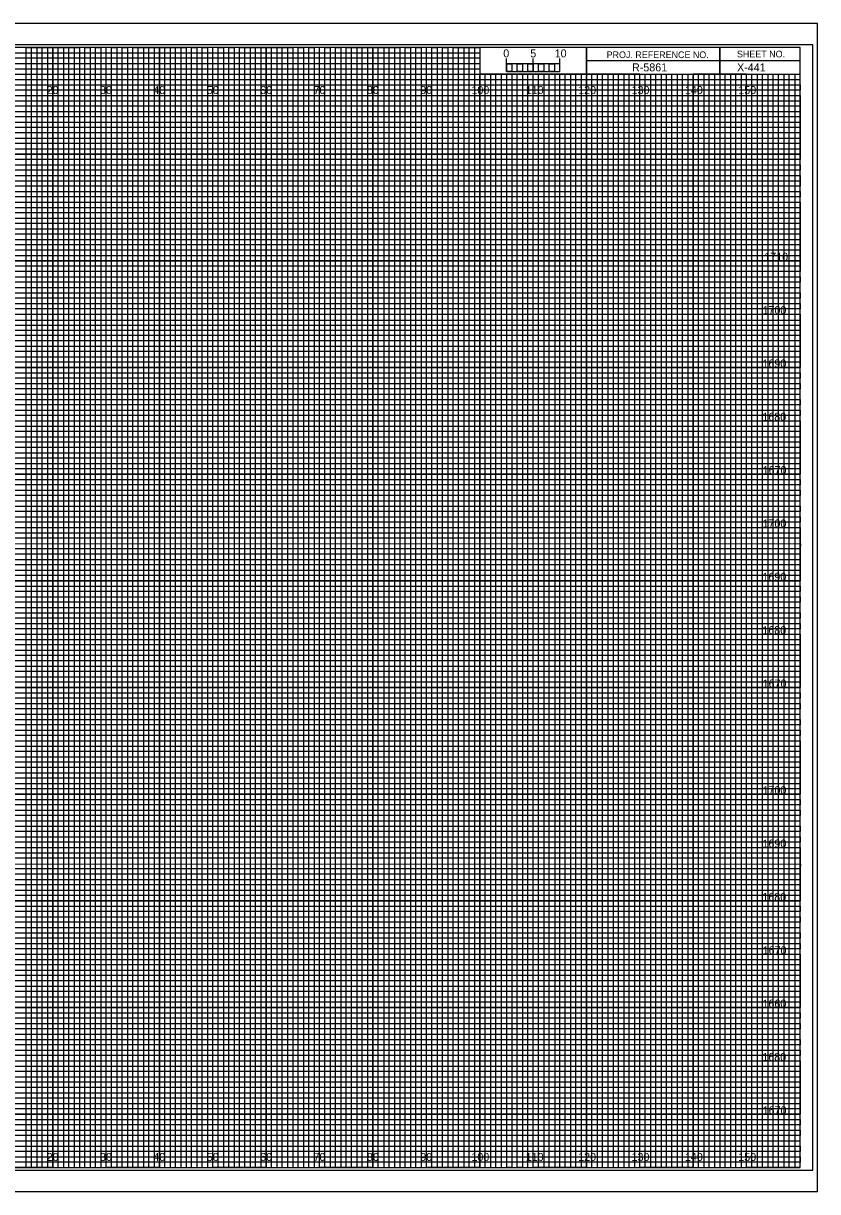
# Model space of a CAD drawing. Extents: x -13 to 323, y -5 to 1314.
# Drawn here: x 174.5 to 323.3, y -4.5 to 214.5 of the extents above; entities that cross this region are included whole.
import ezdxf

# ---------------------------------------------------------------- set-up
doc = ezdxf.new("R2010")
doc.units = 0
for name, color, linetype in [('Prop XS Bar Scale Labels', 7, 'Continuous'), ('Prop XS Project Number', 7, 'Continuous'), ('Prop XS Sheet Number', 7, 'Continuous'), ('Raster_Level_0', 7, 'Continuous'), ('Scratch_Level_3', 7, 'Continuous'), ('Sheet Cross Section CELL', 7, 'Continuous'), ('Sheet Cross Section Grid Major CELL', 7, 'Continuous'), ('Sheet Cross Section Grid Middle CELL', 7, 'Continuous'), ('Sheet Cross Section Grid Minor 1 CELL', 7, 'Continuous'), ('Sheet Cross Section Grid Minor 2 CELL', 7, 'Continuous'), ('Sheet Cross Section Scale CELL', 7, 'Continuous'), ('Sheet Cutting Line CELL', 7, 'Continuous'), ('Sheet DOT Grid CELL', 7, 'Continuous'), ('Sheet Plot Border Inside CELL', 7, 'Continuous'), ('Sheet Plot Border Outside CELL', 7, 'Continuous')]:
    doc.layers.add(name, color=color, linetype=linetype)

msp = doc.modelspace()

# ---------------------------------------------------------------- linework, layer by layer
at = {"layer": 'Sheet Cross Section CELL'}
for p, q in [((305, 210), (305, 205)), ((305, 205), (305, 210)), ((280, 207.5), (280, 205)), ((320, 207.49), (280, 207.49)), ((280, 205), (320, 205))]:
    msp.add_line(p, q, dxfattribs=at)
for points in [[(320, 210), (0, 210), (0, 0), (320, 0)], [(280, 210), (260, 210), (260, 205.03), (280, 205.03)], [(320, 210), (280, 210), (280, 205), (320, 205)]]:
    msp.add_lwpolyline(points, close=True, dxfattribs=at)
at = {"layer": 'Sheet Cross Section Grid Major CELL'}
for p, q in [((190, 210), (180, 210)), ((180, 210), (180, 0)), ((190, 0), (190, 210)), ((210, 210), (200, 210)), ((200, 210), (200, 0)), ((210, 0), (210, 210)), ((230, 210), (220, 210)), ((220, 210), (220, 0)), ((230, 0), (230, 210)), ((250, 210), (240, 210)), ((240, 210), (240, 0)), ((250, 0), (250, 210)), ((260, 210), (260, 0)), ((270, 0), (270, 205)), ((290, 205), (280, 205)), ((280, 205), (280, 0)), ((290, 0), (290, 205)), ((310, 205), (300, 205)), ((300, 205), (300, 0)), ((310, 0), (310, 205)), ((180, 0), (170, 0)), ((200, 0), (190, 0)), ((220, 0), (210, 0)), ((240, 0), (230, 0)), ((260, 0), (250, 0)), ((280, 0), (270, 0)), ((300, 0), (290, 0)), ((320, 0), (310, 0)), ((320, 0), (320, 0))]:
    msp.add_line(p, q, dxfattribs=at)
for points in [[(0, 200), (320, 200), (320, 190), (0, 190)], [(0, 180), (320, 180), (320, 170), (0, 170)], [(0, 160), (320, 160), (320, 150), (0, 150)], [(0, 140), (320, 140), (320, 130), (0, 130)], [(0, 120), (320, 120), (320, 110), (0, 110)], [(0, 100), (320, 100), (320, 90), (0, 90)], [(0, 80), (320, 80), (320, 70), (0, 70)], [(0, 60), (320, 60), (320, 50), (0, 50)], [(0, 40), (320, 40), (320, 30), (0, 30)], [(0, 20), (320, 20), (320, 10), (0, 10)]]:
    msp.add_lwpolyline(points, dxfattribs=at)
at = {"layer": 'Sheet Cross Section Grid Middle CELL'}
for points in [[(165, 0), (175, 0), (175, 210), (185, 210), (185, 0), (195, 0), (195, 210), (205, 210), (205, 0), (215, 0), (215, 210), (225, 210), (225, 0), (235, 0), (235, 210), (245, 210), (245, 0), (255, 0), (255, 210), (259.93, 210), (260, 210), (260, 205), (264.99, 205), (264.99, 0), (275, 0), (275, 205), (285, 205), (285, 0), (295, 0), (295, 205), (305, 205), (305, 0), (315, 0), (315, 205)], [(0, 205), (275, 205)], [(0, 185), (320, 185), (320, 195), (0, 195)], [(0, 165), (320, 165), (320, 175), (0, 175)], [(0, 145), (320, 145), (320, 155), (0, 155)], [(0, 125), (320, 125), (320, 135), (0, 135)], [(0, 105), (320, 105), (320, 115), (0, 115)], [(0, 85), (320, 85), (320, 95), (0, 95)], [(0, 65), (320, 65), (320, 75), (0, 75)], [(0, 45), (320, 45), (320, 55), (0, 55)], [(0, 25), (320, 25), (320, 35), (0, 35)], [(0, 5), (320, 5), (320, 15), (0, 15)]]:
    msp.add_lwpolyline(points, dxfattribs=at)
at = {"layer": 'Sheet Cross Section Grid Minor 1 CELL'}
for p, q in [((0, 209), (260, 209)), ((260, 209), (260, 207.98)), ((260, 207.98), (0, 207.98)), ((0, 207), (260, 207)), ((260, 205.89), (0, 205.89)), ((260, 207), (260, 205.89)), ((0, 204), (320, 204))]:
    msp.add_line(p, q, dxfattribs=at)
for points in [[(0, 203), (270, 203), (320, 203), (320, 202), (0, 202)], [(0, 201), (320, 201), (320, 199), (0, 199)], [(0, 198), (320, 198), (320, 197), (0, 196.98)], [(0, 196), (320, 196), (320, 194), (0, 194)], [(0, 193), (320, 193), (320, 192), (0, 192)], [(0, 191), (320, 191), (320, 189), (0, 189)], [(0, 188), (320, 188), (320, 187), (0, 187)], [(0, 186), (320, 186), (320, 184), (0, 184)], [(0, 183), (320, 183), (320, 182), (0, 182)], [(0, 181), (320, 181), (320, 179), (0, 179)], [(0, 178), (320, 178), (320, 177), (0, 177)], [(0, 176), (320, 176), (320, 173.95), (320, 173), (320, 172), (0, 172)], [(0, 174), (320, 174), (320, 173), (0, 173)], [(0, 171), (320, 171), (320, 169), (0, 169.03)], [(0, 169.03), (320, 169), (320, 168), (0, 168)], [(0, 167), (320, 167), (320, 166), (0, 166)], [(0, 164), (320, 164), (320, 163), (0, 163)], [(0, 162), (320, 162), (320, 161), (0, 161)], [(-0.07, 158.89), (320, 158.89), (320, 157.88), (-0.07, 157.88)], [(0, 157), (320, 157), (320, 156), (0, 156)], [(0, 154), (320, 154), (320, 153), (0, 153)], [(0, 152), (320, 152), (320, 151), (0, 151)], [(0, 149), (320, 149), (320, 148), (0, 148)], [(0, 147), (320, 147), (320, 146), (0, 146)], [(0, 144), (320, 144), (320, 143), (0, 143)], [(0, 142), (320, 142), (320, 141), (0, 141)], [(0, 139), (320, 139), (319.99, 137.98), (0, 138)], [(0, 137), (320, 137), (320, 136), (0, 136)], [(0, 134), (320, 134), (320, 133), (0, 133)], [(0, 132), (320, 132), (320, 131), (0, 131)], [(0, 129), (320, 129), (320, 128), (0, 128)], [(0, 127), (320, 127), (320, 126), (0, 126)], [(0, 124), (320, 124), (320, 123), (0, 123)], [(0, 122), (320, 122), (320, 121), (0, 121)], [(0, 119), (320, 119), (320, 118), (0, 118)], [(0, 116.99), (320.07, 116.91), (320, 116), (0, 116)], [(0, 114), (320, 114), (320, 113), (0, 113)], [(0, 112), (320, 112), (320, 111), (0, 111)], [(0, 109), (320, 109), (320, 108), (0, 108)], [(0, 107), (320, 107), (320, 106), (0, 106)], [(0, 104), (320, 104), (320, 103), (0, 103)], [(0, 102), (320, 102), (320, 101), (0, 101)], [(0, 99), (320, 99), (320, 98), (0, 98)], [(0, 97), (320, 97), (320, 96), (0, 96)], [(0, 94), (320, 94), (320, 93), (0, 93)], [(0, 92), (320, 92), (320, 91), (0, 91)], [(0, 89), (320, 89), (320, 88), (0, 88)], [(0, 87), (320, 87), (320, 86), (0, 86)], [(0, 84), (320, 84), (320, 83), (0, 83)], [(0, 82), (320, 82), (320, 81), (0, 81)], [(0, 79), (320, 79), (319.99, 77.98), (0, 78)], [(0, 77), (320, 77), (320, 76), (0, 76)], [(0, 74), (320, 74), (320, 73), (0, 73)], [(0, 72), (320, 72), (320, 71), (0, 71)], [(0, 69), (320, 69), (320, 68), (0, 68)], [(0, 67), (320, 67), (320, 66), (0, 66)], [(0, 64), (320, 64), (320, 63), (0, 63)], [(0, 62), (320, 62), (320, 61), (0, 61)], [(0, 59), (320, 59), (320, 58), (0, 58)], [(0, 56.99), (320.07, 56.91), (320, 56), (0, 56)], [(0, 54), (320, 54), (320, 53), (0, 53)], [(0, 52), (320, 52), (320, 51), (0, 51)], [(0, 49), (320, 49), (320, 48), (0, 48)], [(0, 47), (320, 47), (320, 46), (0, 46)], [(0, 44), (320, 44), (320, 43), (0, 43)], [(0, 42), (320, 42), (320, 41), (0, 41)], [(0, 39), (320, 39), (320, 38), (0, 38)], [(0, 37), (320, 37), (320, 36), (0, 36)], [(0, 34), (320, 34), (320, 33), (0, 33)], [(0, 32), (320, 32), (320, 31), (0, 31)], [(0, 29), (320, 29), (320, 28), (0, 28)], [(0, 27), (320, 27), (320, 26), (0, 26)], [(0, 24), (320, 24), (320, 23), (0, 23)], [(0, 22), (320, 22), (320, 21), (0, 21)], [(0, 19), (320, 19), (320, 18), (0, 18)], [(0, 17), (320, 17), (320, 16), (0, 16)], [(0, 14), (320, 14), (320, 13), (0, 13)], [(0, 12), (320, 12), (320, 11), (0, 11)], [(0, 9), (320, 9), (320, 8), (0, 8)], [(0, 7), (320, 7), (320, 6), (0, 6)], [(0, 4), (320, 4), (320, 3), (0, 3)], [(0, 2), (320, 2), (320, 1), (0, 1)]]:
    msp.add_lwpolyline(points, dxfattribs=at)
at = {"layer": 'Sheet Cross Section Grid Minor 2 CELL'}
for p, q in [((267, 205), (266.01, 205)), ((266.01, 205), (266.01, 0)), ((267, 0), (267, 205)), ((269, 205), (268, 205)), ((268, 205), (268, 0)), ((269, 0), (269, 205)), ((266.01, 0), (265, 0)), ((268, 0), (267, 0))]:
    msp.add_line(p, q, dxfattribs=at)
for points in [[(175, 0), (176, 0), (176, 210), (177, 210), (177, 0)], [(177, 0), (178, 0), (178, 210), (179, 210), (179, 0)], [(180, 0), (181, 0), (181, 210), (182, 210), (182, 0)], [(182, 0), (183, 0), (183, 210), (184, 210), (184, 0)], [(185, 0), (186, 0), (186, 210), (187, 210), (187, 0)], [(187, 0), (188, 0), (188, 210), (189, 210), (189, 0)], [(190, 0), (191, 0), (191, 210), (192, 210), (192, 0)], [(192, 0), (193, 0), (193, 210), (194, 210), (194, 0)], [(195, 0), (196, 0), (196, 210), (197, 210), (197, 0)], [(197, 0), (198, 0), (198, 210), (199, 210), (199, 0)], [(200, 0), (201, 0), (201, 210), (202, 210), (202, 0)], [(202, 0), (203, 0), (203, 210), (204, 210), (204, 0)], [(205, 0), (206, 0), (206, 210), (207, 210), (207, 0)], [(207, 0), (208, 0), (208, 210), (209, 210), (209, 0)], [(210, 0), (211, 0), (211, 210), (212, 210), (212, 0)], [(212, 0), (213, 0), (213, 210), (214, 210), (214, 0)], [(215, 0), (216, 0), (216, 210), (217, 210), (217, 0)], [(217, 0), (218, 0), (218, 210), (219, 210), (219, 0)], [(220, 0), (221, 0), (221, 210), (222, 210), (222, 0)], [(222, 0), (223, 0), (223, 210), (224, 210), (224, 0)], [(225, 0), (226, 0), (226, 210), (227, 210), (227, 0)], [(227, 0), (228, 0), (228, 210), (229, 210), (229, 0)], [(230, 0), (231, 0), (231, 210), (232, 210), (232, 0)], [(232, 0), (233, 0), (233, 210), (234, 210), (234, 0)], [(235, 0), (236, 0), (236, 210), (237, 210), (237, 0)], [(237, 0), (238, 0), (238, 210), (239, 210), (239, 0)], [(240, 0), (241, 0), (241, 210), (242, 210), (242, 0)], [(242, 0), (243, 0), (243, 210), (244, 210), (244, 0)], [(245, 0), (246, 0), (246, 210), (247, 210), (247, 0)], [(247, 0), (248, 0), (248, 210), (249, 210), (249, 0)], [(250, 0), (251, 0), (251, 210), (252, 210), (252, 0)], [(252, 0), (253, 0), (253, 210), (254, 210), (254, 0)], [(255, 0), (256, 0), (256, 210), (257, 210), (257, 0)], [(257, 0), (258, 0), (258, 210), (259, 210), (259, 0)], [(260, 0), (261, 0), (261, 205), (262.02, 205), (262.02, 0)], [(262, 0), (263, 0), (263, 205), (263.99, 205), (263.99, 0)], [(270, 0), (270.98, 0), (270.98, 205), (272, 205), (272, 0)], [(272, 0), (273, 0), (273, 205), (274.05, 205), (274.05, 0)], [(275, 0), (276, 0), (276, 205), (277, 205), (277, 0)], [(277, 0), (278, 0), (278, 205), (279, 205), (279, 0)], [(280, 0), (281, 0), (281, 205), (282, 205), (282, 0)], [(282, 0), (283, 0), (283, 205), (284, 205), (284, 0)], [(285, 0), (286, 0), (286, 205), (287, 205), (287, 0)], [(287, 0), (288, 0), (288, 205), (289, 205), (289, 0)], [(290, 0), (291, 0), (291, 205), (292, 205), (292, 0)], [(292, 0), (293, 0), (293, 205), (294, 205), (294, 0)], [(295, 0), (296, 0), (296, 205), (297, 205), (297, 0)], [(297, 0), (298, 0), (298, 205), (299, 205), (299, 0)], [(300, 0), (301, 0), (301, 205), (302, 205), (302, 0)], [(302, 0), (303, 0), (303, 205), (304, 205), (304, 0)], [(305, 0), (306, 0), (306, 205), (307, 205), (307, 0)], [(307, 0), (308, 0), (308, 205), (309, 205), (309, 0)], [(310, 0), (311, 0), (311, 205), (312, 205), (312, 0)], [(312, 0), (313, 0), (313, 205), (314, 205), (314, 0)], [(315, 0), (316, 0), (316, 205), (317, 205), (317, 0)], [(317, 0), (318, 0), (318, 205), (319, 205), (319, 0)]]:
    msp.add_lwpolyline(points, dxfattribs=at)
at = {"layer": 'Sheet Cross Section Scale CELL'}
for p, q in [((265, 205.49), (265, 207.9)), ((265, 206.9), (265, 207.9)), ((270, 205.49), (270, 207.9)), ((275, 205.49), (275, 207.9)), ((275, 206.9), (275, 207.9))]:
    msp.add_line(p, q, dxfattribs=at)
for points in [[(275, 206.9), (265, 206.9), (265, 205.49), (275, 205.49)], [(265, 206.9), (266, 206.9), (266, 205.49), (265, 205.49)], [(267, 206.9), (268, 206.9), (268, 205.49), (267, 205.49)], [(269, 206.9), (270, 206.9), (270, 205.49), (269, 205.49)], [(271, 206.9), (272, 206.9), (272, 205.49), (271, 205.49)], [(273, 206.9), (274, 206.9), (274, 205.49), (273, 205.49)]]:
    msp.add_lwpolyline(points, close=True, dxfattribs=at)
at = {"layer": 'Sheet Cutting Line CELL'}
for p, q in [((323.3, 214.5), (-13.4, 214.5)), ((-13.4, -4.5), (323.3, -4.5))]:
    msp.add_line(p, q, dxfattribs=at)
at = {"layer": 'Sheet DOT Grid CELL'}
for p, q in [((180, 0), (180, 210)), ((190, 0), (190, 210)), ((200, 0), (200, 210)), ((210, 0), (210, 210)), ((220, 0), (220, 210)), ((230, 0), (230, 210)), ((240, 0), (240, 210)), ((250, 0), (250, 210)), ((260, 0), (260, 204.69)), ((270, 0), (270, 204.69)), ((280, 0), (280, 204.69)), ((290, 0), (290, 204.69)), ((300, 0), (300, 204.69)), ((310, 0), (310, 204.69)), ((0, 200), (320, 200)), ((0, 190), (320, 190)), ((0, 180), (320, 180)), ((0, 170), (320, 170)), ((0, 160), (320, 160)), ((0, 150), (320, 150)), ((0, 140), (320, 140)), ((0, 130), (320, 130)), ((0, 120), (320, 120)), ((0, 110), (320, 110)), ((0, 100), (320, 100)), ((0, 90), (320, 90)), ((0, 80), (320, 80)), ((0, 70), (320, 70)), ((0, 60), (320, 60)), ((0, 50), (320, 50)), ((0, 40), (320, 40)), ((0, 30), (320, 30)), ((0, 20), (320, 20)), ((0, 10), (320, 10))]:
    msp.add_line(p, q, dxfattribs=at)
at = {"layer": 'Sheet Plot Border Inside CELL'}
msp.add_lwpolyline([(-10.8, -0.5), (322.4, -0.5), (322.4, 210.5), (-10.8, 210.5)], close=True, dxfattribs=at)
at = {"layer": 'Sheet Plot Border Outside CELL'}
msp.add_lwpolyline([(-13.4, -4.5), (323.3, -4.5), (323.3, 214.5), (-13.4, 214.5)], close=True, dxfattribs=at)

# ---------------------------------------------------------------- texts
at = {"layer": 'Prop XS Bar Scale Labels'}
for s, p in [('5', (269.47, 208.12)), ('10', (274.04, 208.12))]:
    msp.add_text(s, height=1.5, dxfattribs=at).set_placement(p)
at = {"layer": 'Prop XS Project Number'}
msp.add_text('R-5861', height=1.5, dxfattribs=at).set_placement((288.53, 205.5))
at = {"layer": 'Prop XS Sheet Number'}
msp.add_text('X-441', height=1.5, dxfattribs=at).set_placement((308.21, 205.5))
at = {"layer": 'Raster_Level_0'}
for s, p in [('20', (178.86, 201.25)), ('30', (188.86, 201.25)), ('40', (198.86, 201.25)), ('50', (208.86, 201.25)), ('60', (218.86, 201.25)), ('70', (228.86, 201.25)), ('80', (238.86, 201.25)), ('90', (248.86, 201.25)), ('100', (258.44, 201.25)), ('110', (268.62, 201.25)), ('120', (278.44, 201.25)), ('130', (288.44, 201.25)), ('140', (298.44, 201.25)), ('150', (308.44, 201.25)), ('20', (178.86, 1.25)), ('30', (188.86, 1.25)), ('40', (198.86, 1.25)), ('50', (208.86, 1.25)), ('60', (218.86, 1.25)), ('70', (228.86, 1.25)), ('80', (238.86, 1.25)), ('90', (248.86, 1.25)), ('100', (258.44, 1.25)), ('110', (268.62, 1.25)), ('120', (278.44, 1.25)), ('130', (288.44, 1.25)), ('140', (298.44, 1.25)), ('150', (308.44, 1.25))]:
    msp.add_text(s, height=1.5, dxfattribs=at).set_placement(p)
at = {"layer": 'Scratch_Level_3'}
for s, p in [('1710', (313.31, 170)), ('1700', (312.98, 160)), ('1690', (312.97, 150)), ('1680', (312.95, 140)), ('1670', (313, 130)), ('1700', (312.98, 120)), ('1690', (312.97, 110)), ('1680', (312.95, 100)), ('1670', (313, 90)), ('1700', (312.98, 70)), ('1690', (312.97, 60)), ('1680', (312.95, 50)), ('1670', (313, 40)), ('1660', (312.97, 30)), ('1680', (312.95, 20)), ('1670', (313, 10))]:
    msp.add_text(s, height=1.5, dxfattribs=at).set_placement(p)
at = {"layer": 'Sheet Cross Section CELL'}
for s, p in [('PROJ. REFERENCE NO.', (283.77, 207.99)), ('SHEET NO.', (308.19, 208.12))]:
    msp.add_text(s, height=1.25, dxfattribs=at).set_placement(p)
at = {"layer": 'Sheet Cross Section Scale CELL'}
msp.add_text('0', height=1.5, dxfattribs=at).set_placement((264.41, 208.12))

doc.saveas('drawing.dxf')
